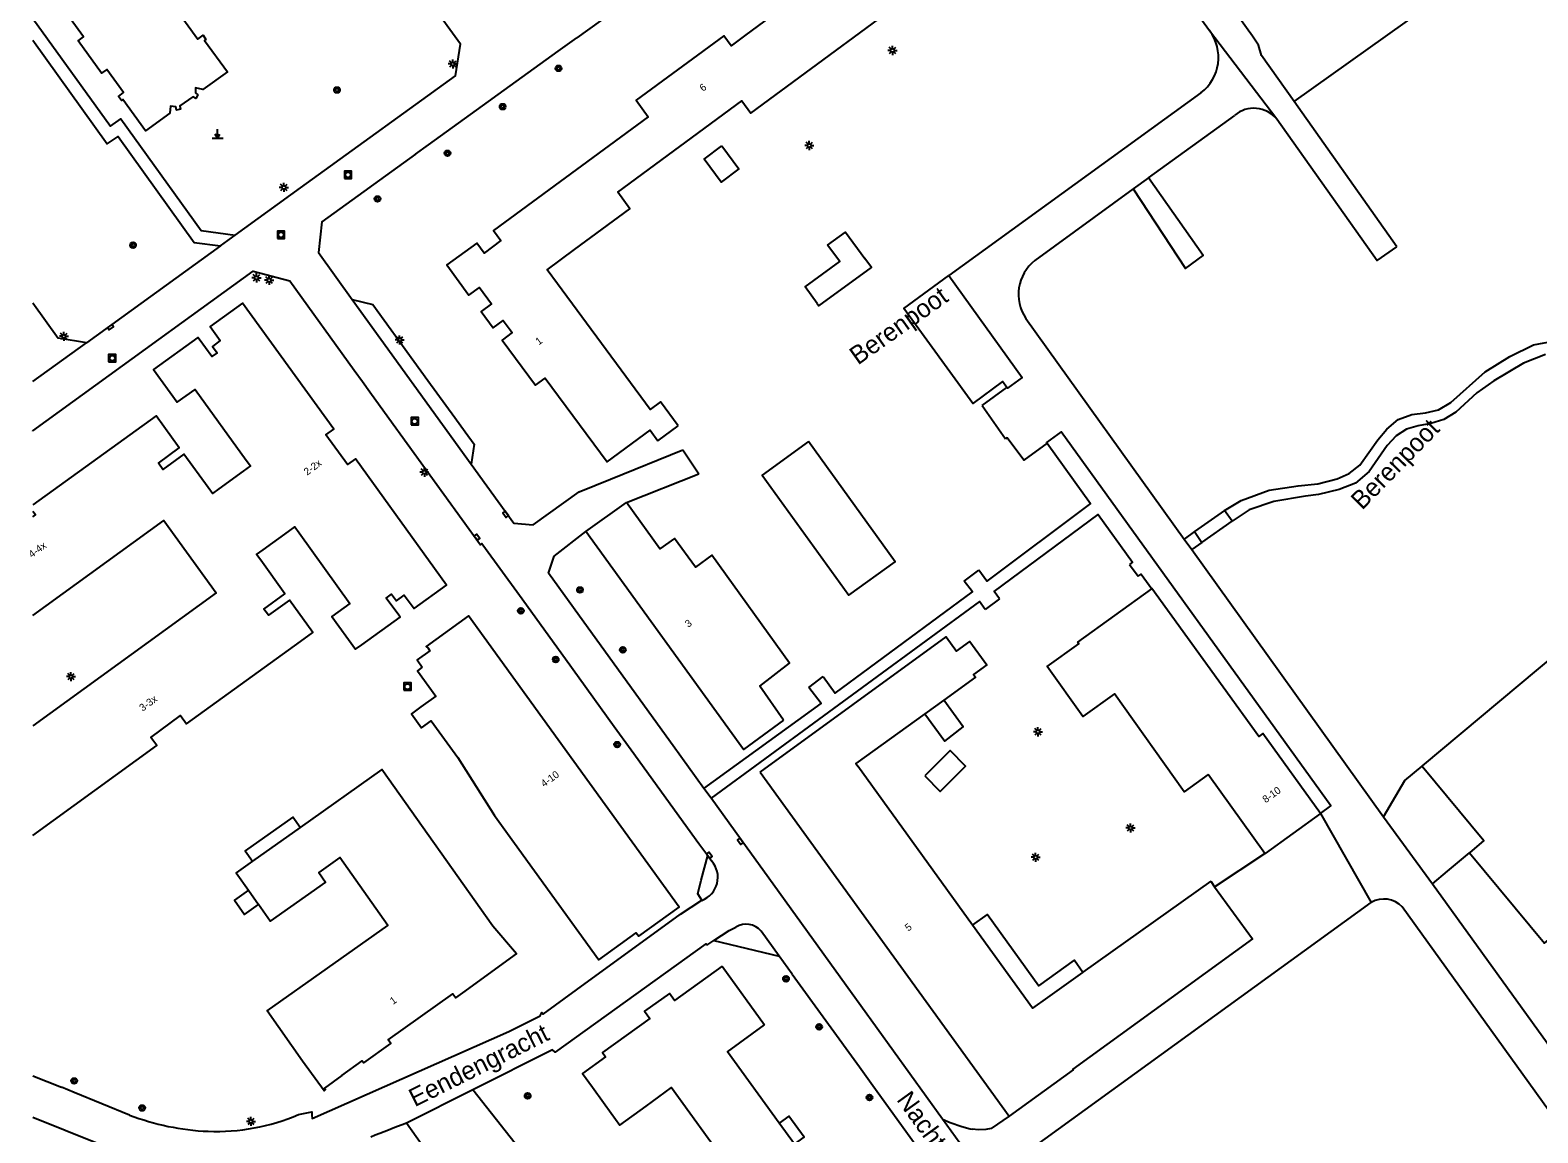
# Model space of a CAD drawing. Extents: x 141000 to 143000, y 400580 to 403500.
# Drawn here: x 140999.6 to 141206, y 402763.7 to 402914.6 of the extents above; entities that cross this region are included whole.
import ezdxf

# ---------------------------------------------------------------- set-up
doc = ezdxf.new("R2010")
doc.units = 0
for name, color, linetype in [('gg-afsc-erfafscheiding', 7, 'Continuous'), ('gg-afsc-hekwerk', 7, 'Continuous'), ('gg-anno-huisnummerreeks BGT', 7, 'Continuous'), ('gg-anno-openbare ruimte label', 7, 'Continuous'), ('gg-bbg-bijgebouw', 7, 'Continuous'), ('gg-bbg-hoofdgebouw', 7, 'Continuous'), ('gg-bbg-luifel en loopbrug', 7, 'Continuous'), ('gg-knt-bronhoudergrens', 7, 'Continuous'), ('gg-knt-verharding', 7, 'Continuous'), ('gg-knt-verharding nz', 7, 'Continuous'), ('gg-kwrk-kunstwerk niveau 01', 7, 'Continuous'), ('gt-grn-vlakafsluiter', 7, 'Continuous'), ('gt-grn-weggrens', 7, 'Continuous'), ('gt-symb-boom', 7, 'Continuous'), ('gt-symb-kolk', 7, 'Continuous'), ('gt-symb-lichtmast', 7, 'Continuous'), ('gt-symb-markant object', 7, 'Continuous'), ('gt-symb-rioolschacht', 7, 'Continuous')]:
    doc.layers.add(name, color=color, linetype=linetype)

# ---------------------------------------------------------------- blocks, each defined once
blk = doc.blocks.new('gt0-LMAST')
at = {"layer": 'gt-symb-lichtmast'}
for p, q in [((-0.18, 0.17), (-0.45, 0.44)), ((-0.01, 0.25), (-0.01, 0.62)), ((0.17, 0.17), (0.44, 0.44)), ((-0.26, 0), (-0.63, 0)), ((-0.18, -0.18), (-0.45, -0.45)), ((-0.01, -0.25), (-0.01, -0.63)), ((0.44, -0.45), (0.17, -0.18)), ((0.24, 0), (0.62, 0))]:
    blk.add_line(p, q, dxfattribs=at)
blk.add_circle((-0.01, 0), 0.25, dxfattribs=at)
blk = doc.blocks.new('gt0-BOOM')
at = {"layer": 'gt-symb-boom'}
for radius in [0.4, 0.2]:
    blk.add_circle((0, 0), radius, dxfattribs=at)
blk = doc.blocks.new('gt0-KOLK')
at = {"layer": 'gt-symb-kolk'}
blk.add_lwpolyline([(0, 0), (0.37, 0), (0.37, 0.4), (-0.38, 0.4), (-0.38, 0), (0, 0)], dxfattribs=at)
blk = doc.blocks.new('gt0-RS')
at = {"layer": 'gt-symb-rioolschacht'}
blk.add_lwpolyline([(-0.5, -0.5), (0.5, -0.5), (0.5, 0.5), (-0.5, 0.5)], close=True, dxfattribs=at)
blk.add_circle((0, 0), 0.375, dxfattribs=at)
blk = doc.blocks.new('gt0-MARKOB')
at = {"layer": 'gt-symb-markant object'}
for p, q in [((-0.75, 0), (0.75, 0)), ((0, 0), (-0.3, 0.52)), ((0, 0), (0, 1.2)), ((0, 0), (0.3, 0.52))]:
    blk.add_line(p, q, dxfattribs=at)

msp = doc.modelspace()

# ---------------------------------------------------------------- linework, layer by layer
at = {"layer": 'gg-afsc-erfafscheiding'}
for p, q in [((141079.6, 402819.34), (141081.91, 402816.15)), ((141005.66, 402769.25), (141003.93, 402769.96))]:
    msp.add_line(p, q, dxfattribs=at)
at = {"layer": 'gg-afsc-hekwerk'}
for p, q in [((141129.93, 402863.25), (141133.16, 402858.69)), ((141127.48, 402839.24), (141129.5, 402840.72)), ((141150.13, 402841.52), (141151.3, 402839.89)), ((141132.32, 402836.81), (141130.37, 402835.34)), ((141161.77, 402797.41), (141168.65, 402801.97))]:
    msp.add_line(p, q, dxfattribs=at)
at = {"layer": 'gg-bbg-bijgebouw'}
for points in [[(141094.32, 402898.8), (141096.66, 402895.66), (141094.22, 402893.84), (141091.88, 402896.98), (141094.32, 402898.8)], [(141108.8, 402885.2), (141111.24, 402886.99), (141113.87, 402883.38)], [(141107.37, 402877.23), (141105.72, 402879.49), (141110.45, 402882.95), (141108.8, 402885.2)], [(141107.37, 402877.23), (141107.61, 402876.9), (141114.78, 402882.14), (141113.87, 402883.38)]]:
    msp.add_lwpolyline(points, dxfattribs=at)
at = {"layer": 'gg-bbg-hoofdgebouw'}
for p, q in [((141085.56, 402858.44), (141088.35, 402860.49)), ((141075.71, 402846.03), (141081.25, 402850.01)), ((141124.7, 402822.96), (141122.1, 402821.09)), ((141128.64, 402792.13), (141112.94, 402813.91)), ((141099.57, 402813.1), (141133.65, 402766)), ((141168.65, 402801.97), (141160.86, 402812.75)), ((141036.6, 402805.52), (141030.07, 402800.9)), ((141161.24, 402798.15), (141143.75, 402785.71)), ((141161.24, 402798.15), (141161.77, 402797.41)), ((141029.52, 402796.92), (141030.9, 402794.96)), ((141094.34, 402786.54), (141100.16, 402778.51)), ((141104.26, 402762.16), (141102.16, 402765.06))]:
    msp.add_line(p, q, dxfattribs=at)
for points in [[(141011.53, 402928.71), (141022.6, 402913.4), (141023.31, 402913.92), (141023.71, 402913.36), (141023.52, 402913.23), (141026.67, 402908.92), (141023.29, 402906.49), (141022.26, 402906.74), (141022.26, 402906.03), (141022.61, 402905.76), (141022.31, 402905.28), (141021.93, 402905.52), (141020.11, 402904.25), (141020.21, 402903.81), (141019.68, 402903.68), (141019.58, 402904.12), (141018.87, 402904.23), (141018.78, 402903.25), (141015.42, 402900.83), (141012.32, 402905.14), (141012.13, 402905), (141011.72, 402905.57), (141012.44, 402906.09), (141010.15, 402909.24), (141009.43, 402908.72), (141006.22, 402913.18), (141006.94, 402913.7), (141001.33, 402921.45)], [(141088.35, 402860.49), (141085.94, 402863.76), (141084.52, 402862.71), (141071.84, 402879.92), (141070.42, 402881.85), (141074.15, 402884.6), (141081.74, 402890.19), (141080.07, 402892.47), (141097.05, 402904.97), (141098.3, 402903.28), (141124.07, 402922.27)], [(141101.08, 402916.56), (141097.43, 402913.85), (141095.58, 402912.49), (141094.57, 402913.86), (141082.57, 402905.04), (141084.22, 402902.78), (141063.06, 402887.19), (141064.06, 402885.82), (141061.78, 402884.11), (141060.78, 402885.49), (141056.69, 402882.53), (141059.7, 402878.35), (141061.14, 402879.39), (141062.79, 402877.18), (141061.36, 402876.12), (141063.02, 402873.87), (141064.39, 402874.88), (141065.6, 402873.23), (141064.23, 402872.22), (141068.79, 402866.03), (141070.15, 402867.02), (141078.61, 402855.56), (141084.49, 402859.89), (141085.56, 402858.44)], [(141000, 402804.4), (141016.97, 402816.74), (141016.17, 402817.85), (141020.23, 402820.82), (141021.06, 402819.69), (141036.65, 402830.97), (141038.34, 402832.18), (141035.15, 402836.62), (141032.25, 402834.55), (141031.64, 402835.4), (141034.52, 402837.49), (141031.22, 402842.09), (141030.64, 402842.89), (141031.53, 402843.52), (141035, 402846.02), (141035.88, 402846.65), (141036.45, 402845.85), (141043.4, 402836.17), (141040.94, 402834.39), (141044.16, 402829.91), (141045.02, 402830.53), (141050.27, 402834.32), (141050.11, 402834.55), (141048.39, 402836.92), (141049.11, 402837.44), (141049.77, 402836.54), (141050.85, 402837.31), (141052.21, 402835.47), (141056.65, 402838.67), (141044.16, 402855.96), (141043.07, 402855.17), (141040.12, 402859.24), (141041.22, 402860.03), (141028.71, 402877.28), (141024.29, 402874.07), (141025.64, 402872.16), (141024.58, 402871.35), (141025.22, 402870.49), (141024.5, 402869.96), (141022.78, 402872.33), (141022.61, 402872.57), (141016.52, 402868.18), (141019.77, 402863.71), (141022.22, 402865.46), (141029.22, 402855.8), (141029.8, 402855.01), (141028.8, 402854.29), (141025.48, 402851.88), (141024.58, 402851.22), (141023.99, 402852.03), (141020.68, 402856.61), (141017.8, 402854.52), (141017.19, 402855.36), (141020.05, 402857.48), (141016.87, 402861.87), (141000, 402849.67)], [(141000, 402848.01), (141000.36, 402848.28), (141000, 402848.78)], [(141102.78, 402820.22), (141099.52, 402824.87), (141103.57, 402828), (141092.95, 402842.76), (141090.71, 402841.15), (141087.86, 402845.08), (141085.83, 402843.64), (141081.25, 402850.01)], [(141000, 402834.54), (141017.95, 402847.54), (141025.11, 402837.61), (141000, 402819.42)], [(141102.78, 402820.22), (141097.29, 402816.21), (141075.71, 402846.03)], [(141253.46, 402835.38), (141252.26, 402834.38), (141248.5, 402838.88), (141227.88, 402821.7), (141222.3, 402828.38), (141217.42, 402824.34), (141211.33, 402831.63), (141190.16, 402813.95), (141190.17, 402813.93)], [(141160.86, 402812.75), (141157.62, 402810.41), (141148.06, 402823.82), (141143.71, 402820.72), (141138.83, 402827.56), (141143.19, 402830.67), (141143.05, 402830.86), (141153.16, 402838.19)], [(141176.25, 402807.43), (141168.37, 402818.38), (141167.8, 402817.99), (141153.18, 402838.2), (141153.16, 402838.19)], [(141053.32, 402827.46), (141052.65, 402826.97), (141055.16, 402823.49), (141053.12, 402822.02), (141051.82, 402821.07), (141053.22, 402819.14), (141054.55, 402820.11), (141057.81, 402815.61), (141058.18, 402815.11), (141063.2, 402807.14), (141077.49, 402787.41), (141082.61, 402791.12), (141082.94, 402790.66), (141088.49, 402794.63), (141059.64, 402834.47), (141053.87, 402830.29), (141054.14, 402830.07), (141054.34, 402829.7), (141052.61, 402828.45), (141053.32, 402827.46)], [(141099.57, 402813.1), (141125.02, 402831.62), (141126.45, 402829.66), (141128.24, 402830.96), (141130.6, 402827.79), (141128.78, 402826.46), (141129.04, 402826.1), (141124.7, 402822.96)], [(141122.1, 402821.09), (141112.67, 402814.29), (141112.94, 402813.91)], [(141190.17, 402813.93), (141198.63, 402803.72), (141196.63, 402802.07), (141196.66, 402802.03)], [(141058.85, 402782.91), (141066.22, 402788.21), (141062.97, 402792.01), (141047.8, 402813.44), (141036.6, 402805.52)], [(141176.25, 402807.43), (141168.67, 402801.95), (141168.65, 402801.97)], [(141042.31, 402771.57), (141039.92, 402769.83), (141040.07, 402769.66), (141040, 402769.59), (141039.88, 402769.49), (141036.94, 402773.53), (141032.07, 402780.41), (141048.6, 402792.11), (141042.03, 402801.39), (141039.15, 402799.34), (141040.07, 402798.04), (141032.51, 402792.69), (141030.9, 402794.96)], [(141196.66, 402802.03), (141206.9, 402789.67), (141210.15, 402792.38)], [(141030.07, 402800.9), (141027.83, 402799.31), (141029.52, 402796.92)], [(141161.77, 402797.41), (141166.97, 402790.26), (141142.35, 402772.45), (141142.42, 402772.35), (141133.65, 402766)], [(141143.75, 402785.71), (141143.67, 402785.65), (141138.87, 402782.23), (141136.83, 402780.78), (141128.64, 402792.13)], [(141094.34, 402786.54), (141087.86, 402781.83), (141087.17, 402782.8), (141083.74, 402780.37), (141084.44, 402779.39), (141077.98, 402774.71), (141078.38, 402774.14), (141075.24, 402771.85), (141076.6, 402769.97), (141078.13, 402767.86), (141079.19, 402766.4), (141080.35, 402764.8), (141083.95, 402767.4), (141087.45, 402769.93), (141105.01, 402745.66)], [(141042.31, 402771.57), (141045.1, 402773.6), (141045.32, 402773.33), (141049.03, 402775.97), (141048.66, 402776.48), (141057.52, 402782.75), (141057.89, 402782.22), (141058.85, 402782.91)], [(141102.16, 402765.06), (141095.09, 402774.83), (141100.16, 402778.51)]]:
    msp.add_lwpolyline(points, dxfattribs=at)
at = {"layer": 'gg-bbg-luifel en loopbrug'}
for points in [[(141106.16, 402858.35), (141099.83, 402853.75), (141111.71, 402837.3), (141118.05, 402841.88), (141106.16, 402858.35)], [(141122.1, 402821.09), (141124.83, 402817.32), (141127.36, 402819.27), (141124.7, 402822.96)], [(141122.08, 402812.6), (141124.18, 402810.46), (141127.67, 402813.91), (141125.56, 402816.04), (141122.08, 402812.6)], [(141036.6, 402805.52), (141035.59, 402806.95), (141029.06, 402802.33), (141030.07, 402800.9)], [(141029.52, 402796.92), (141027.6, 402795.56), (141028.99, 402793.6), (141030.9, 402794.96)], [(141128.64, 402792.13), (141130.67, 402793.6), (141137.7, 402783.85), (141142.59, 402787.34), (141143.75, 402785.71)], [(141104.26, 402762.16), (141105.58, 402763.12), (141103.48, 402766.02), (141102.16, 402765.06)]]:
    msp.add_lwpolyline(points, dxfattribs=at)
at = {"layer": 'gg-knt-bronhoudergrens'}
msp.add_lwpolyline([(141067.89, 402759.91), (141060.07, 402754.29), (141059.02, 402753.96), (141051.17, 402765.06)], dxfattribs=at)
at = {"layer": 'gg-knt-verharding'}
for p, q in [((141082.48, 402919.34), (141074.46, 402913.56)), ((141157.6, 402919.39), (141161.06, 402914.56)), ((141071.93, 402911.74), (141074.46, 402913.56)), ((141054.19, 402898.95), (141071.93, 402911.74)), ((141159.89, 402906.05), (141125.4, 402881.03)), ((141186.7, 402884.97), (141172.66, 402904.85)), ((141152.7, 402894.4), (141164.52, 402902.97)), ((141052.41, 402897.67), (141054.19, 402898.95)), ((141150.62, 402892.93), (141137.16, 402883.1)), ((141025.69, 402885.11), (141007.37, 402871.85)), ((141043.72, 402877.79), (141060.03, 402855.25)), ((141000, 402877.32), (141003.5, 402872.48)), ((141135.93, 402875.18), (141157.59, 402844.99)), ((141007.37, 402871.85), (141003.5, 402872.48)), ((141129.93, 402863.25), (141133.34, 402865.71)), ((141079.07, 402853.19), (141088.97, 402857.21)), ((141081.25, 402850.01), (141091.15, 402853.92)), ((141071.38, 402842.66), (141075.71, 402846.03)), ((141158.99, 402846), (141157.59, 402844.99)), ((141157.59, 402844.99), (141158.64, 402843.54)), ((141160, 402844.52), (141158.64, 402843.54)), ((141061.62, 402844.2), (141066.61, 402837.31)), ((141158.64, 402843.54), (141184.87, 402806.99)), ((141066.61, 402837.31), (141072.91, 402828.59)), ((141087.65, 402816.71), (141075.43, 402833.62)), ((141072.91, 402828.59), (141079.6, 402819.34)), ((141081.91, 402816.15), (141091.18, 402803.34)), ((141091.87, 402810.86), (141087.65, 402816.71)), ((141097.77, 402802.69), (141092.85, 402809.51)), ((141091.18, 402803.34), (141092.38, 402801.67)), ((141091.51, 402798.33), (141092.38, 402801.67)), ((141092.38, 402801.67), (141092.93, 402800.91)), ((141099.92, 402799.71), (141097.77, 402802.69)), ((141111.34, 402783.9), (141099.92, 402799.71)), ((141191.61, 402797.8), (141193.65, 402799.54)), ((141191.61, 402797.8), (141211.89, 402769.63)), ((141136.76, 402761.6), (141183.21, 402795.27)), ((141207.47, 402766.83), (141187.44, 402794.64)), ((141102.18, 402787.92), (141099.69, 402791.35)), ((141092.27, 402789.41), (141093.23, 402790.04)), ((141093.23, 402790.04), (141102.18, 402787.92)), ((141103.96, 402785.46), (141102.18, 402787.92)), ((141103.96, 402785.46), (141113.15, 402772.76)), ((141113.36, 402781.11), (141111.34, 402783.9)), ((141124.54, 402765.62), (141113.36, 402781.11)), ((141113.15, 402772.76), (141114.99, 402770.21)), ((141000, 402771.55), (141003.93, 402769.96)), ((141114.99, 402770.21), (141129.15, 402750.66)), ((141013.22, 402766.17), (141005.66, 402769.25)), ((141060.23, 402769.6), (141051.17, 402765.06)), ((141000, 402765.89), (141008.86, 402762.31)), ((141133.26, 402753.55), (141124.54, 402765.62))]:
    msp.add_line(p, q, dxfattribs=at)
for points in [[(141027.72, 402886.58), (141036.67, 402893.06), (141038.3, 402894.24), (141057.86, 402908.39), (141058.57, 402912.71), (141036.38, 402943.26), (141032.61, 402948.44), (141015.1, 402972.54)], [(141172.66, 402904.85), (141168.19, 402911.18), (141167.76, 402912.56), (141166.97, 402913.79), (141155.48, 402929.78)], [(141000, 402916.23), (141010.64, 402901.5), (141012.07, 402902.47), (141023.04, 402887.22), (141027.72, 402886.58)], [(141000, 402913.24), (141010.2, 402899.05), (141011.67, 402900.08), (141022.1, 402885.59), (141025.69, 402885.11)], [(141170.26, 402902.49), (141184, 402883.09), (141186.7, 402884.97)], [(141052.41, 402897.67), (141039.57, 402888.41), (141039.12, 402884.21), (141043.72, 402877.79)], [(141150.62, 402892.93), (141157.8, 402882.02), (141160.2, 402883.78), (141152.7, 402894.4)], [(141000, 402859.77), (141000.02, 402859.78), (141001.85, 402861.11), (141017.28, 402872.29), (141020.41, 402874.56), (141030.19, 402881.65), (141035.18, 402880.3), (141044, 402868.11), (141045.13, 402866.54), (141046.14, 402865.15), (141048.74, 402861.55), (141061.28, 402844.21), (141061.48, 402844.39), (141061.62, 402844.2)], [(141133.34, 402865.71), (141132.75, 402866.53), (141128.68, 402863.55), (141119.23, 402876.52), (141125.4, 402881.03)], [(141043.72, 402877.79), (141046.57, 402877.08), (141052.17, 402869.34), (141054.08, 402866.7), (141057.76, 402861.62), (141059.19, 402859.65), (141060.41, 402857.96), (141060.03, 402855.25)], [(141163.14, 402848.91), (141165.42, 402850.25), (141169.22, 402851.66), (141173.19, 402852.28), (141175.91, 402852.55), (141178.55, 402853.23), (141180.16, 402853.95), (141181.65, 402855.1), (141184.11, 402858.57), (141185.35, 402860.01), (141186.91, 402861.36), (141188.74, 402862.01), (141190.63, 402862.24), (141192.43, 402862.65), (141194.1, 402863.67), (141198.8, 402867.89), (141202.15, 402869.98), (141205.43, 402871.57), (141208.12, 402872.05)], [(141207.05, 402870.26), (141204.04, 402869.07), (141199.98, 402866.63), (141197.64, 402864.98), (141194.8, 402862.33), (141193.16, 402861.33), (141191.36, 402860.82), (141189.63, 402860.49), (141188.03, 402860.02), (141186.6, 402859.11), (141185.4, 402857.81), (141182.94, 402854.25), (141181.03, 402852.62), (141178.8, 402851.77), (141175.97, 402851.1), (141174.22, 402850.86), (141169.87, 402850.11), (141166.49, 402848.99), (141164.17, 402847.42)], [(141138.84, 402858.09), (141144.78, 402849.84), (141130.58, 402839.21), (141129.5, 402840.72)], [(141138.84, 402858.09), (141135.67, 402855.79), (141133.39, 402858.85), (141133.16, 402858.69)], [(141060.03, 402855.25), (141065.84, 402847.18), (141068.48, 402846.92), (141074.78, 402851.45), (141079.07, 402853.19)], [(141132.32, 402836.81), (141131.57, 402837.82), (141145.84, 402848.33), (141150.54, 402841.81), (141150.13, 402841.52)], [(141075.43, 402833.62), (141070.59, 402840.32), (141071.38, 402842.66)], [(141108.18, 402826.19), (141109.84, 402823.9), (141128.61, 402837.76), (141127.48, 402839.24)], [(141151.3, 402839.89), (141151.71, 402840.19), (141153.16, 402838.19)], [(141130.37, 402835.34), (141129.57, 402836.43), (141092.85, 402809.51)], [(141091.87, 402810.86), (141107.9, 402822.49), (141106.22, 402824.68)], [(141184.87, 402806.99), (141187.79, 402811.95), (141190.17, 402813.93)], [(141091.58, 402795.55), (141091.01, 402796.42), (141091.51, 402798.33)], [(141036.39, 402766.23), (141038.18, 402766.59), (141038.21, 402766.16), (141038.24, 402765.67), (141065.17, 402777.62), (141069.47, 402779.75), (141069.7, 402780.19), (141069.87, 402779.97), (141074.41, 402783.32), (141088.64, 402793.65), (141091.58, 402795.55)], [(141093.23, 402790.04), (141095.34, 402791.41), (141096.24, 402791.88)], [(141092.27, 402789.41), (141092.13, 402789.58), (141071.51, 402774.78), (141071.13, 402775.07), (141060.23, 402769.6)], [(141124.54, 402765.62), (141125.55, 402765.15), (141127.17, 402764.58), (141128.29, 402764.27), (141128.6, 402764.24)], [(141133.65, 402766), (141131.17, 402764.33), (141130.43, 402764.18), (141129.43, 402764.16), (141128.6, 402764.24)]]:
    msp.add_lwpolyline(points, dxfattribs=at)
for centre, radius, start, end in [((141156.19, 402910.9), 6.1, 307.343, 36.8966), ((141167.15, 402899.87), 4.07, 40.0588, 130.3264), ((141140.81, 402878.48), 5.89, 128.3229, 214.0706), ((141090.42, 402798.69), 3.35, 290.205, 41.4507), ((141184.93, 402792.26), 3.47, 43.4897, 119.7809), ((141097.65, 402789.54), 2.73, 41.4269, 121.0134), ((141025.45, 402798.08), 34.17, 249.0374, 267.5666), ((141025, 402793.2), 29.28, 268.0401, 292.8925), ((141236.9, 402281.83), 517.7, 111.0249, 111.607)]:
    msp.add_arc(centre, radius, start, end, dxfattribs=at)
at = {"layer": 'gg-knt-verharding nz'}
for p, q in [((141152.7, 402894.4), (141150.62, 402892.93)), ((141092.85, 402809.51), (141091.87, 402810.86)), ((141184.87, 402806.99), (141191.61, 402797.8))]:
    msp.add_line(p, q, dxfattribs=at)
for points in [[(141125.4, 402881.03), (141135.44, 402867.1), (141133.4, 402865.63), (141133.34, 402865.71)], [(141176.25, 402807.43), (141177.69, 402808.47), (141140.78, 402859.65), (141138.76, 402858.19), (141138.84, 402858.09)]]:
    msp.add_lwpolyline(points, dxfattribs=at)
at = {"layer": 'gg-kwrk-kunstwerk niveau 01'}
for p, q in [((141163.14, 402848.91), (141158.99, 402846)), ((141164.17, 402847.42), (141163.14, 402848.91)), ((141160, 402844.52), (141164.17, 402847.42)), ((141158.99, 402846), (141160, 402844.52))]:
    msp.add_line(p, q, dxfattribs=at)
at = {"layer": 'gt-grn-vlakafsluiter'}
for p, q in [((141172.66, 402904.85), (141212.2, 402933.08)), ((141088.97, 402857.21), (141091.15, 402853.92)), ((141106.22, 402824.68), (141108.18, 402826.19)), ((141176.25, 402807.43), (141183.21, 402795.27)), ((141193.65, 402799.54), (141196.66, 402802.03)), ((141067.89, 402759.91), (141060.23, 402769.6))]:
    msp.add_line(p, q, dxfattribs=at)
at = {"layer": 'gt-grn-weggrens'}
for p, q in [((141161.06, 402914.56), (141170.26, 402902.49)), ((141025.69, 402885.11), (141027.72, 402886.58)), ((141000, 402866.53), (141007.37, 402871.85))]:
    msp.add_line(p, q, dxfattribs=at)

# ---------------------------------------------------------------- block references
at = {"layer": 'gt-symb-boom'}
for p in [(141071.95, 402909.4), (141041.64, 402906.44), (141064.31, 402904.16), (141056.78, 402897.78), (141047.18, 402891.53), (141013.73, 402885.21), (141074.9, 402838.02), (141066.8, 402835.16), (141080.77, 402829.83), (141071.58, 402828.5), (141079.99, 402816.86), (141103.1, 402784.81), (141107.65, 402778.24), (141005.66, 402770.83), (141067.74, 402768.79), (141114.54, 402768.57), (141014.98, 402767.13)]:
    msp.add_blockref('gt0-BOOM', p, dxfattribs=at)
at = {"layer": 'gt-symb-kolk'}
for p, rotation in [((141010.52, 402874.14), -144.10492590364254), ((141064.88, 402848.5), 125.73843171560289), ((141060.63, 402845.11), -54.12273170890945), ((141097.01, 402803.74), 125.83692607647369), ((141092.43, 402801.6), -53.38996367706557)]:
    msp.add_blockref('gt0-KOLK', p, dxfattribs=dict(at, rotation=rotation))
at = {"layer": 'gt-symb-lichtmast'}
for p in [(141057.49, 402910), (141117.68, 402911.85), (141106.3, 402898.84), (141034.38, 402893.11), (141030.63, 402880.73), (141032.36, 402880.41), (141004.27, 402872.73), (141050.23, 402872.24), (141053.61, 402854.14), (141005.24, 402826.16), (141137.6, 402818.62), (141150.26, 402805.45), (141137.28, 402801.44), (141029.87, 402765.3)]:
    msp.add_blockref('gt0-LMAST', p, dxfattribs=at)
at = {"layer": 'gt-symb-markant object'}
msp.add_blockref('gt0-MARKOB', (141025.29, 402899.86), dxfattribs=at)
at = {"layer": 'gt-symb-rioolschacht'}
for p in [(141043.15, 402894.83), (141033.98, 402886.62), (141010.89, 402869.75), (141052.28, 402861.1), (141051.29, 402824.79)]:
    msp.add_blockref('gt0-RS', p, dxfattribs=at)

# ---------------------------------------------------------------- texts
at = {"layer": 'gg-anno-huisnummerreeks BGT'}
for s, rotation, p in [('6', 36.3, (141091.72, 402906.18)), ('1', 36.3, (141069.26, 402871.48)), ('2-2x', 35.9, (141037.55, 402853.65)), ('4-4x', 36, (140999.87, 402842.36)), ('3', 35.9, (141089.72, 402832.83)), ('3-3x', 36.2, (141015.04, 402821.35)), ('4-10', 35.9, (141069.99, 402810.98)), ('8-10', 35.6, (141168.76, 402808.82)), ('5', 35.9, (141119.83, 402791.26)), ('1', 35.2, (141049.32, 402781.23))]:
    msp.add_text(s, height=1, rotation=rotation, dxfattribs=at).set_placement(p)
at = {"layer": 'gg-anno-openbare ruimte label'}
for s, rotation, p in [('Berenpoot', 35.4, (141112.95, 402868.73)), ('Berenpoot', 45.7, (141181.96, 402848.87)), ('Eendengracht', 26.6, (141052.29, 402767.22)), ('Nachtegaallaan', 305.8, (141118.15, 402768.26))]:
    msp.add_text(s, height=2.5, rotation=rotation, dxfattribs=at).set_placement(p)

doc.saveas('drawing.dxf')
